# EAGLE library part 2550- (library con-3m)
3M (TM) Pak 100 4-Wall Header Source: 3M
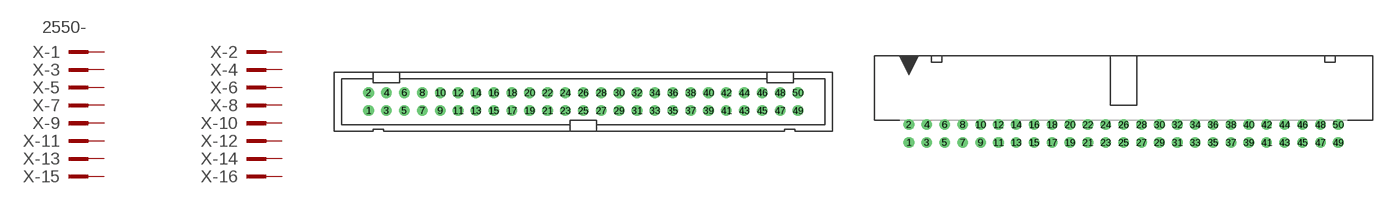
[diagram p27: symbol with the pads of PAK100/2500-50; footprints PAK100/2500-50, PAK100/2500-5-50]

Designator prefix X; gates -1=PINV -2=PIN -3=PIN -4=PIN -5=PIN -6=PIN -7=PIN -8=PIN -9=PIN -10=PIN -11=PIN -12=PIN -13=PIN -14=PIN -15=PIN -16=PIN -17=PIN -18=PIN -19=PIN -20=PIN -21=PIN -22=PIN -23=PIN -24=PIN -25=PIN -26=PIN -27=PIN -28=PIN -29=PIN -30=PIN -31=PIN -32=PIN -33=PIN -34=PIN -35=PIN -36=PIN -37=PIN -38=PIN -39=PIN -40=PIN -41=PIN -42=PIN -43=PIN -44=PIN -45=PIN -46=PIN -47=PIN -48=PIN -49=PIN -50=PIN

## 2550- (OC_FARNELL: unknown; OC_NEWARK: unknown)  [PAK100/2500-50]
1  -1:KL  pas
2  -2:KL  pas
3  -3:KL  pas
4  -4:KL  pas
5  -5:KL  pas
6  -6:KL  pas
7  -7:KL  pas
8  -8:KL  pas
9  -9:KL  pas
10  -10:KL  pas
11  -11:KL  pas
12  -12:KL  pas
13  -13:KL  pas
14  -14:KL  pas
15  -15:KL  pas
16  -16:KL  pas
17  -17:KL  pas
18  -18:KL  pas
19  -19:KL  pas
20  -20:KL  pas
21  -21:KL  pas
22  -22:KL  pas
23  -23:KL  pas
24  -24:KL  pas
25  -25:KL  pas
26  -26:KL  pas
27  -27:KL  pas
28  -28:KL  pas
29  -29:KL  pas
30  -30:KL  pas
31  -31:KL  pas
32  -32:KL  pas
33  -33:KL  pas
34  -34:KL  pas
35  -35:KL  pas
36  -36:KL  pas
37  -37:KL  pas
38  -38:KL  pas
39  -39:KL  pas
40  -40:KL  pas
41  -41:KL  pas
42  -42:KL  pas
43  -43:KL  pas
44  -44:KL  pas
45  -45:KL  pas
46  -46:KL  pas
47  -47:KL  pas
48  -48:KL  pas
49  -49:KL  pas
50  -50:KL  pas

## 2550-5 (OC_FARNELL: 1788696; OC_NEWARK: unknown)  [PAK100/2500-5-50]
Pads as for PAK100/2500-50

## Footprint PAK100/2500-50 (pad centres in mm)
3M (TM) Pak 100 4-Wall Header Straight Source: 3M
drill 1 pad 1.422 round: 1 -30.48,-1.27; 2 -30.48,1.27; 3 -27.94,-1.27; 4 -27.94,1.27; 5 -25.4,-1.27; 6 -25.4,1.27; 7 -22.86,-1.27; 8 -22.86,1.27; 9 -20.32,-1.27; 10 -20.32,1.27; 11 -17.78,-1.27; 12 -17.78,1.27; 13 -15.24,-1.27; 14 -15.24,1.27; 15 -12.7,-1.27; 16 -12.7,1.27; 17 -10.16,-1.27; 18 -10.16,1.27; 19 -7.62,-1.27; 20 -7.62,1.27; 21 -5.08,-1.27; 22 -5.08,1.27; 23 -2.54,-1.27; 24 -2.54,1.27; 25 0,-1.27; 26 0,1.27; 27 2.54,-1.27; 28 2.54,1.27; 29 5.08,-1.27; 30 5.08,1.27; 31 7.62,-1.27; 32 7.62,1.27; 33 10.16,-1.27; 34 10.16,1.27; 35 12.7,-1.27; 36 12.7,1.27; 37 15.24,-1.27; 38 15.24,1.27; 39 17.78,-1.27; 40 17.78,1.27; 41 20.32,-1.27; 42 20.32,1.27; 43 22.86,-1.27; 44 22.86,1.27; 45 25.4,-1.27; 46 25.4,1.27; 47 27.94,-1.27; 48 27.94,1.27; 49 30.48,-1.27; 50 30.48,1.27

## Footprint PAK100/2500-5-50 (pad centres in mm)
3M (TM) Pak 100 4-Wall Header Right Angle Source: 3M
drill 1 pad 1.422 round: 1 -30.48,-1.27; 2 -30.48,1.27; 3 -27.94,-1.27; 4 -27.94,1.27; 5 -25.4,-1.27; 6 -25.4,1.27; 7 -22.86,-1.27; 8 -22.86,1.27; 9 -20.32,-1.27; 10 -20.32,1.27; 11 -17.78,-1.27; 12 -17.78,1.27; 13 -15.24,-1.27; 14 -15.24,1.27; 15 -12.7,-1.27; 16 -12.7,1.27; 17 -10.16,-1.27; 18 -10.16,1.27; 19 -7.62,-1.27; 20 -7.62,1.27; 21 -5.08,-1.27; 22 -5.08,1.27; 23 -2.54,-1.27; 24 -2.54,1.27; 25 0,-1.27; 26 0,1.27; 27 2.54,-1.27; 28 2.54,1.27; 29 5.08,-1.27; 30 5.08,1.27; 31 7.62,-1.27; 32 7.62,1.27; 33 10.16,-1.27; 34 10.16,1.27; 35 12.7,-1.27; 36 12.7,1.27; 37 15.24,-1.27; 38 15.24,1.27; 39 17.78,-1.27; 40 17.78,1.27; 41 20.32,-1.27; 42 20.32,1.27; 43 22.86,-1.27; 44 22.86,1.27; 45 25.4,-1.27; 46 25.4,1.27; 47 27.94,-1.27; 48 27.94,1.27; 49 30.48,-1.27; 50 30.48,1.27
